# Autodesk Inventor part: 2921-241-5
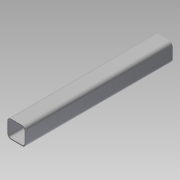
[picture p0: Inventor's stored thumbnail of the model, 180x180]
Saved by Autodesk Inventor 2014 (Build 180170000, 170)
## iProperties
Company: NHTSA/VRTC
Created: 2011-11
Part Number: 2921-241-5
Material: Steel
Document SubType Name: Modeling
Designer: Dave Walker
Density: 7.85 g/cm^3
Project: CHILD SIDE IMPACT SLED
Description: T.S. 2" x 2" x 1/8" x 409.7mm (16.13")
Mass: 1803.32 g
Surface Area: 1458.28 cm^2
Volume: 229.722 cm^3
Stock Number: IMPACTOR FRAME TUBE 5
Appearance: Steel
Author: Dave Walker
Title: Impactor Frame Tube 5
Subject: Child Side Impact Sled
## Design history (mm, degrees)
node "Sketch1"
node "2921-105-51"
node "2921-105-5"
node "Base1"
